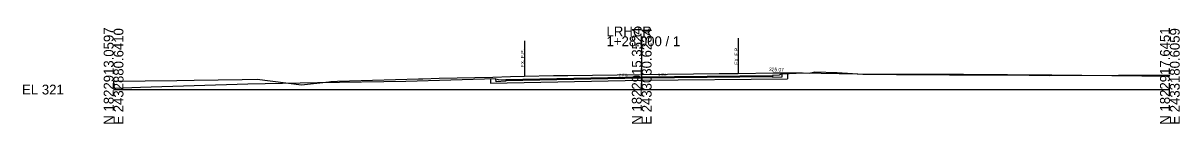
# Model space of a CAD drawing. Extents: x 2432865 to 2441203, y 1814550 to 1826842.
# Drawn here: x 2439603.6 to 2439932.1, y 1822808.5 to 1822836.2 of the extents above; entities that cross this region are included whole.
import ezdxf

# ---------------------------------------------------------------- set-up
doc = ezdxf.new("R2010")
doc.units = 0
for name, color, linetype in [('no plot', 7, 'Continuous'), ('X_TRANS_EOP', 7, 'Continuous'), ('X_TRANS_TX', 7, 'Continuous'), ('XS_CELL', 7, 'Continuous'), ('XS_P_CURB_GUTTER', 7, 'Continuous'), ('XS_P_FINISHED_GRADE', 7, 'Continuous'), ('XS_P_SUBGRADE_GRANULAR', 7, 'Continuous'), ('XS_P_SUBGRADE_PAVEMENT', 7, 'Continuous'), ('XS_P_TX_FS_BS', 7, 'Continuous'), ('XS_X_GROUND', 7, 'Continuous')]:
    doc.layers.add(name, color=color, linetype=linetype)

msp = doc.modelspace()

# ---------------------------------------------------------------- linework, layer by layer
at = {"layer": 'X_TRANS_EOP'}
for p, q in [((2439745.94, 1822832.12), (2439745.94, 1822822.12)), ((2439806.68, 1822832.87), (2439806.68, 1822822.87))]:
    msp.add_line(p, q, dxfattribs=at)
at = {"layer": 'XS_CELL'}
for p, q in [((2439779.27, 1822818.22), (2439779.27, 1822833.36)), ((2439629.27, 1822818.22), (2439779.27, 1822818.22)), ((2439779.27, 1822818.22), (2439929.27, 1822818.22))]:
    msp.add_line(p, q, dxfattribs=at)
at = {"layer": 'XS_P_CURB_GUTTER'}
for p, q in [((2439737.86, 1822821.27), (2439737.86, 1822821.28)), ((2439737.86, 1822821.28), (2439737.86, 1822821.28)), ((2439737.86, 1822821.28), (2439737.87, 1822821.28)), ((2439737.91, 1822820.46), (2439737.86, 1822821.27)), ((2439737.87, 1822821.28), (2439737.87, 1822821.28)), ((2439740.65, 1822820.57), (2439737.91, 1822820.46)), ((2439740.63, 1822821.07), (2439740.65, 1822820.57)), ((2439816.41, 1822822.21), (2439816.43, 1822821.71)), ((2439816.43, 1822821.71), (2439819.18, 1822821.83)), ((2439819.15, 1822822.65), (2439819.15, 1822822.66)), ((2439819.16, 1822822.65), (2439819.15, 1822822.65)), ((2439819.18, 1822821.83), (2439819.16, 1822822.65)), ((2439819.16, 1822822.65), (2439819.16, 1822822.65))]:
    msp.add_line(p, q, dxfattribs=at)
at = {"layer": 'XS_P_FINISHED_GRADE'}
for p, q in [((2439629.52, 1822818.49), (2439629.3, 1822820.65)), ((2439737.87, 1822821.28), (2439738.57, 1822821.09)), ((2439738.57, 1822821.09), (2439738.6, 1822821.07)), ((2439738.6, 1822821.07), (2439738.63, 1822821.04)), ((2439738.63, 1822820.99), (2439740.63, 1822821.07)), ((2439738.63, 1822821.04), (2439738.63, 1822821.01)), ((2439738.63, 1822821.01), (2439738.63, 1822820.99)), ((2439740.63, 1822821.07), (2439779.27, 1822821.84)), ((2439779.27, 1822821.84), (2439816.41, 1822822.21)), ((2439818.41, 1822822.3), (2439816.41, 1822822.21)), ((2439818.43, 1822822.38), (2439818.41, 1822822.35)), ((2439818.41, 1822822.35), (2439818.41, 1822822.32)), ((2439818.41, 1822822.32), (2439818.41, 1822822.3)), ((2439818.47, 1822822.4), (2439818.43, 1822822.38)), ((2439819.14, 1822822.66), (2439818.47, 1822822.4)), ((2439819.15, 1822822.66), (2439819.14, 1822822.66)), ((2439819.15, 1822822.66), (2439825.14, 1822823.03)), ((2439825.14, 1822823.03), (2439845.55, 1822822.57)), ((2439929.14, 1822822.08), (2439929.24, 1822822.41))]:
    msp.add_line(p, q, dxfattribs=at)
for points in [[(2439737.87, 1822821.28), (2439712.24, 1822820.49), (2439687.15, 1822820.1), (2439667.38, 1822819.77), (2439636.95, 1822818.76), (2439629.52, 1822818.49)], [(2439845.55, 1822822.57), (2439855.59, 1822822.65), (2439870.65, 1822822.63), (2439895.76, 1822822.42), (2439921.29, 1822822.17), (2439929.14, 1822822.08)]]:
    msp.add_lwpolyline(points, dxfattribs=at)
at = {"layer": 'XS_P_SUBGRADE_GRANULAR'}
for p, q in [((2439736.36, 1822821.24), (2439736.36, 1822820.02)), ((2439736.36, 1822820.02), (2439779.29, 1822820.88)), ((2439779.28, 1822820.88), (2439820.66, 1822821.3)), ((2439820.66, 1822822.75), (2439820.66, 1822821.3))]:
    msp.add_line(p, q, dxfattribs=at)
at = {"layer": 'XS_P_SUBGRADE_PAVEMENT'}
for p, q in [((2439740.65, 1822820.78), (2439779.28, 1822821.55)), ((2439779.28, 1822821.55), (2439816.42, 1822821.92))]:
    msp.add_line(p, q, dxfattribs=at)
at = {"layer": 'XS_X_GROUND'}
msp.add_lwpolyline([(2439629.27, 1822820.65), (2439647.26, 1822820.78), (2439652.15, 1822820.91), (2439665.77, 1822821.04), (2439670.07, 1822821.16), (2439682.67, 1822819.55), (2439690.45, 1822820.4), (2439690.96, 1822820.51), (2439692.91, 1822820.59), (2439696.31, 1822820.71), (2439715.86, 1822821.24), (2439717.07, 1822821.27), (2439721.73, 1822821.43), (2439736.95, 1822821.78), (2439741.98, 1822821.92), (2439745.94, 1822822.02), (2439754.26, 1822822.2), (2439758.24, 1822822.27), (2439779.27, 1822822.52), (2439801.31, 1822822.77), (2439806.68, 1822822.77), (2439816.62, 1822822.97), (2439824.93, 1822823), (2439826.86, 1822822.93), (2439828.44, 1822823.27), (2439834.8, 1822823.1), (2439842.06, 1822822.63), (2439851.66, 1822822.54), (2439862.52, 1822822.47), (2439866.64, 1822822.46), (2439889.34, 1822822.31), (2439890.04, 1822822.31), (2439895.16, 1822822.27), (2439914.71, 1822822.36), (2439918.14, 1822822.36), (2439929.27, 1822822.41)], dxfattribs=at)

# ---------------------------------------------------------------- texts
at = {"layer": 'no plot'}
msp.add_text('325.07', height=1, rotation=357.7094, dxfattribs=at).set_placement((2439815.41, 1822823.49))
at = {"layer": 'X_TRANS_TX'}
for p in [(2439745.94, 1822824.52), (2439806.68, 1822825.27)]:
    msp.add_text('EX. E.P.', height=1, rotation=90, dxfattribs=at).set_placement(p)
at = {"layer": 'XS_CELL'}
for s, p in [('N 1822913.0597', (2439629.27, 1822808.22)), ('E 2432880.6410', (2439632.07, 1822808.22)), ('N 1822915.3524', (2439779.27, 1822808.22)), ('E 2433030.6234', (2439782.07, 1822808.22)), ('N 1822917.6451', (2439929.27, 1822808.22)), ('E 2433180.6059', (2439932.07, 1822808.22))]:
    msp.add_text(s, height=2.8, rotation=90, dxfattribs=at).set_placement(p)
for s, p in [('LRHCR', (2439769.27, 1822833.36)), ('1+28.000 / 1', (2439769.27, 1822830.56)), ('EL 321', (2439603.27, 1822816.82))]:
    msp.add_text(s, height=2.8, dxfattribs=at).set_placement(p)
at = {"layer": 'XS_P_TX_FS_BS'}
for s, p in [('-2.0%', (2439772.34, 1822821.98)), ('1.0%', (2439783.92, 1822822.07))]:
    msp.add_text(s, height=0.8, rotation=359.975, dxfattribs=at).set_placement(p)

doc.saveas('drawing.dxf')
